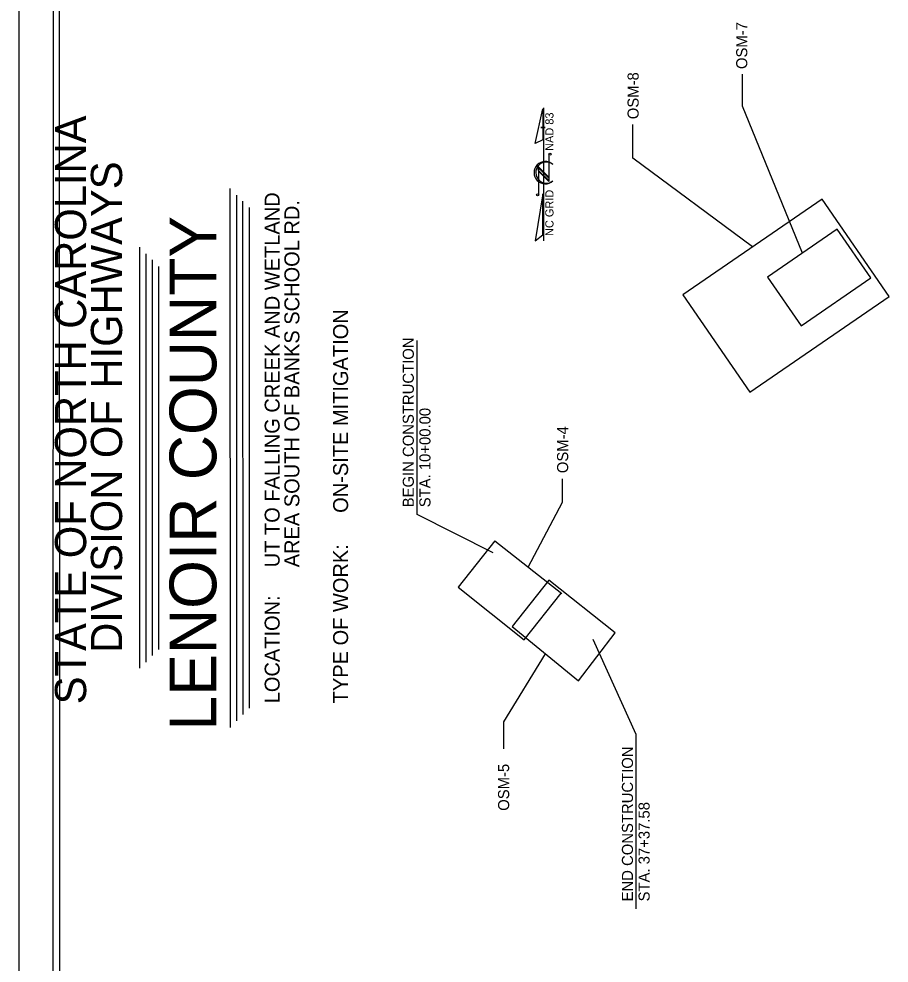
# Model space of a CAD drawing. Extents: x 264770 to 739672, y 157173 to 249791.
# Drawn here: x 726341 to 731047, y 166716 to 171822 of the extents above; entities that cross this region are included whole.
import ezdxf

# ---------------------------------------------------------------- set-up
doc = ezdxf.new("R2010")
doc.units = 0
for name, color, linetype in [('Old_Level_13', 7, 'Continuous'), ('Prop Dimension', 7, 'Continuous'), ('Prop GRAU 350 Approach CELL', 7, 'Continuous'), ('Prop GRAU 350 Trailing CELL', 7, 'Continuous'), ('Prop Lane Arrow Shared Rt and Thru CELL', 7, 'Continuous'), ('Prop_centerline', 7, 'Continuous'), ('Sheet Plot Border Inside CELL', 7, 'Continuous'), ('Sheet Plot Border Outside CELL', 7, 'Continuous'), ('stationing', 7, 'Continuous')]:
    doc.layers.add(name, color=color, linetype=linetype)

msp = doc.modelspace()

# ---------------------------------------------------------------- linework, layer by layer
at = {"layer": 'Old_Level_13'}
msp.add_line((726341.5, 174741.1), (726341.5, 163347.1), dxfattribs=at)
at = {"layer": 'Prop Dimension'}
msp.add_line((729180, 170981.3), (729180, 170981.3), dxfattribs=at)
at = {"layer": 'Prop GRAU 350 Approach CELL'}
for points in [[(726527, 174557.5), (726525.7, 164435.2)], [(726559.4, 174525.1), (726560.8, 164810.5)]]:
    msp.add_lwpolyline(points, dxfattribs=at)
at = {"layer": 'Prop GRAU 350 Trailing CELL'}
for p, q in [((730684.8, 170847.7), (729931, 170330)), ((731047.2, 170320.1), (730684.8, 170847.7)), ((730767, 170684.7), (730390.1, 170425.9)), ((730948.1, 170420.9), (730767, 170684.7)), ((730390.1, 170425.9), (730571.3, 170162.1)), ((730571.3, 170162.1), (730948.1, 170420.9)), ((729931, 170330), (730293.4, 169802.4)), ((730293.4, 169802.4), (731047.2, 170320.1)), ((728915.2, 168999.6), (728716.3, 168748.8)), ((728915.2, 168999.6), (729276.8, 168713.6)), ((729207.6, 168785.9), (729008.7, 168535.1)), ((729565.8, 168501.7), (729207.6, 168785.9)), ((728716.3, 168748.8), (729074.4, 168464.7)), ((729074.4, 168464.7), (729273.4, 168715.4)), ((729008.7, 168535.1), (729366.7, 168242.4)), ((729366.7, 168242.4), (729565.8, 168501.7))]:
    msp.add_line(p, q, dxfattribs=at)
at = {"layer": 'Prop Lane Arrow Shared Rt and Thru CELL'}
for p, q in [((728494.3, 169140.8), (728494.3, 170082.9)), ((728905.8, 168933.8), (728494.3, 169140.8))]:
    msp.add_line(p, q, dxfattribs=at)
msp.add_lwpolyline([(729679.4, 167009.2), (729679.4, 167951.4), (729446.2, 168464.8)], dxfattribs=at)
at = {"layer": 'Prop_centerline'}
for p, q in [((729180, 170621.6), (729180, 171341.5)), ((729207, 171090.7), (729207, 170943.2)), ((729207, 170966.3), (729152.1, 171021.2)), ((729152.1, 171021.2), (729152.1, 170871)), ((729227.4, 171035.8), (729228.3, 171035.4)), ((729228.3, 171035.4), (729227.4, 171035.8)), ((729207, 170947.2), (729152.1, 171002.1)), ((729207, 170947.2), (729152.1, 171002.1)), ((729152.1, 171002.1), (729207, 170947.2)), ((729207, 170943.2), (729152.1, 170998.2))]:
    msp.add_line(p, q, dxfattribs=at)
for points in [[(729134, 171147.9), (729175.2, 171334.8), (729175.2, 171168.7)], [(729152.1, 171002.1), (729152.1, 171015.9), (729207, 170960.5), (729207, 170947.2)], [(729174.3, 170875), (729133.5, 170621.6), (729174.3, 170653.5)]]:
    msp.add_lwpolyline(points, close=True, dxfattribs=at)
for centre in [(729213, 171090.7), (729146.3, 170870.8)]:
    msp.add_circle(centre, 5.87, dxfattribs=at)
for centre, radius, start, end in [((729187.7, 170990.4), 60.5, 47.84, 312.3941), ((729193.5, 170990.5), 56.7, 53.095, 308.6287)]:
    msp.add_arc(centre, radius, start, end, dxfattribs=at)
at = {"layer": 'Sheet Plot Border Inside CELL'}
for p, q in [((727485.5, 167989.8), (727484.2, 170904.4)), ((727519.3, 168026.2), (727519.3, 170869.3)), ((727554.4, 168060), (727553, 170836.9)), ((727588.1, 168093.7), (727588.1, 170801.8)), ((726995.5, 168311.1), (726995.5, 170587.2)), ((727030.6, 168343.5), (727030.6, 170552.1)), ((727064.3, 168378.6), (727064.3, 170518.3)), ((727098.1, 168412.3), (727098.1, 170483.2))]:
    msp.add_line(p, q, dxfattribs=at)
at = {"layer": 'Sheet Plot Border Outside CELL'}
for points in [[(730578.5, 170555.3), (730254.3, 171349.1), (730254.3, 171523.2)], [(730307.9, 170588.9), (729661.6, 171069.4), (729661.6, 171250.1)], [(729096, 168856.6), (729281.6, 169209), (729281.7, 169333.8)], [(729187.7, 168388.8), (728962.7, 168020.6), (728962.7, 167875.1)]]:
    msp.add_lwpolyline(points, dxfattribs=at)
at = {"layer": 'stationing'}
for p, q in [((729164.1, 171235.1), (729182.7, 171235.1)), ((729186.7, 171235.1), (729164.1, 171235.1)), ((729182.7, 171235.1), (729186.7, 171235.1))]:
    msp.add_line(p, q, dxfattribs=at)

# ---------------------------------------------------------------- texts
at = {"layer": 'Prop Dimension'}
for s, height, p in [('STATE OF NORTH CAROLINA', 168.739, (726705.2, 168115.3)), ('DIVISION OF HIGHWAYS', 168.739, (726899.6, 168393.4)), ('UT TO FALLING CREEK AND WETLAND', 80.992, (727751.5, 168856.1)), ('AREA SOUTH OF BANKS SCHOOL RD.', 80.992, (727858.1, 168856.1)), ('LENOIR COUNTY', 253.125, (727409.2, 167973.1)), ('ON-SITE MITIGATION', 80.992, (728121.6, 169150.5)), ('TYPE OF WORK:', 80.992, (728121.6, 168120.7)), ('LOCATION: ', 80.99, (727751.5, 168120.7))]:
    msp.add_text(s, height=height, rotation=90, dxfattribs=at).set_placement(p)
at = {"layer": 'Prop GRAU 350 Approach CELL'}
for s, p in [('NAD 83', (729232.3, 171108.3)), ('NC GRID', (729232.3, 170647.8))]:
    msp.add_text(s, height=44.3, rotation=90, dxfattribs=at).set_placement(p)
at = {"layer": 'Prop Lane Arrow Shared Rt and Thru CELL'}
for s, p in [('OSM-7', (730280.2, 171550.7)), ('OSM-8', (729692.8, 171279.4)), ('BEGIN CONSTRUCTION', (728477.1, 169180.7)), ('STA. 10+00.00', (728567.1, 169180.7)), ('OSM-4', (729311.7, 169365.2)), ('END CONSTRUCTION', (729662.2, 167049.2)), ('OSM-5', (728992.7, 167539.2)), ('STA. 37+37.58', (729752.2, 167049.2))]:
    msp.add_text(s, height=60, rotation=90, dxfattribs=at).set_placement(p)
at = {"layer": 'Sheet Plot Border Outside CELL'}
for rotation, p in [(323.3669, (730307.2, 170589)), (292.2208, (730578, 170555.7)), (242.2253, (729096, 168857.3)), (58.5715, (729187.6, 168388.1))]:
    msp.add_text('D', height=0.6, rotation=rotation, dxfattribs=at).set_placement(p)

doc.saveas('drawing.dxf')
